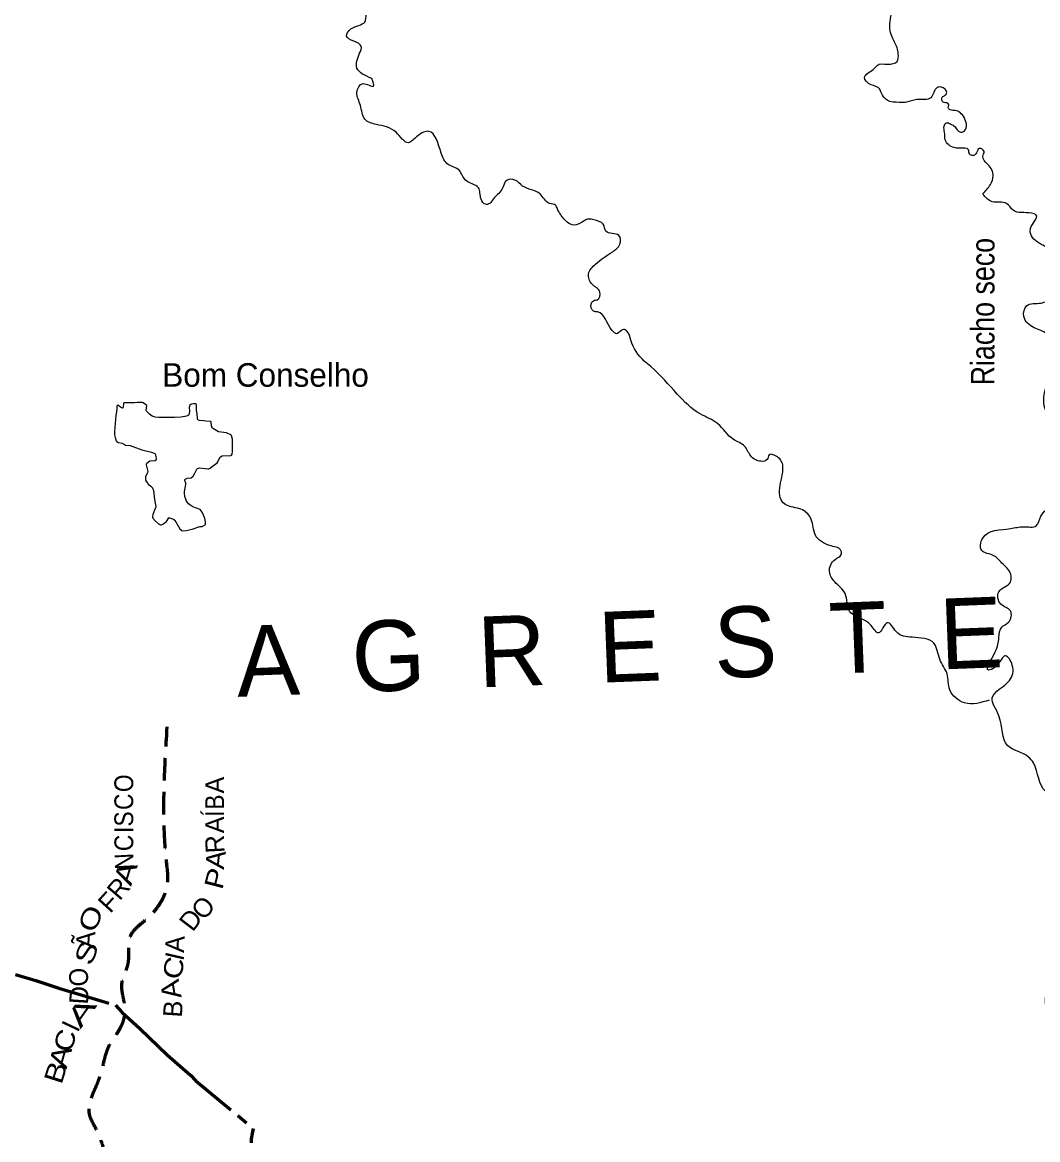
# Model space of a CAD drawing. Extents: x -1643653 to 4543381, y 1624270 to 13878484.
# Drawn here: x 751465 to 773010, y 8971104 to 8994810 of the extents above; entities that cross this region are included whole.
import ezdxf
from ezdxf.enums import TextEntityAlignment as Align

# ---------------------------------------------------------------- set-up
doc = ezdxf.new("R2010")
doc.units = 0
doc.header["$LTSCALE"] = 160
doc.linetypes.add('LONG_DASH_SHORT_DASH', pattern=[9.9, 6, -1.2, 1.5, -1.2])
doc.linetypes.add('MEDIUM_DASHED', pattern=[4.5, 3, -1.5])
for name, color, linetype, lineweight in [('10', 7, 'MEDIUM_DASHED', 60), ('21', 7, 'Continuous', 25), ('24', 7, 'Continuous', 25), ('60', 7, 'Continuous', 13), ('7', 7, 'LONG_DASH_SHORT_DASH', 60)]:
    doc.layers.add(name, color=color, linetype=linetype, lineweight=lineweight)
for name, color, linetype in [('41', 7, 'Continuous'), ('49', 7, 'Continuous'), ('55', 7, 'Continuous')]:
    doc.layers.add(name, color=color, linetype=linetype)

msp = doc.modelspace()

# ---------------------------------------------------------------- linework, layer by layer
at = {"layer": '10'}
msp.add_spline([(753353.8, 8967411.3), (753402.1, 8967459.7), (753447.5, 8967537.9), (753569.9, 8968137.4), (753569.9, 8968618.2), (753685.3, 8969252.9), (753896.8, 8969522.2), (753935.3, 8969791.5), (753646.8, 8970214.6), (753242.9, 8970791.6), (753050.6, 8971291.7), (752896.7, 8971618.7), (753127.5, 8972484.2), (753300.6, 8973080.5), (753550.6, 8973484.4), (753646.8, 8973869.1), (753589.1, 8974215.3), (753589.1, 8974484.5), (753704.5, 8974811.5), (753723.7, 8975177), (753762.2, 8975427), (754089.2, 8975773.2), (754377.7, 8976100.2), (754550.8, 8976561.8), (754531.6, 8976946.5), (754538.8, 8979865.5)], degree=3, dxfattribs=at)
at = {"layer": '21'}
for points in [[(754106.5, 8986680.5), (754028.4, 8986735.9), (754008.6, 8986741.8), (753959.7, 8986746.4), (753911.5, 8986745.8), (753847.3, 8986736.2), (753617.4, 8986734.1), (753610.5, 8986721), (753603, 8986636.5), (753598.5, 8986625.7), (753593.3, 8986622.8), (753548.2, 8986646.6), (753513.2, 8986676.1), (753489.4, 8986684.9), (753479.3, 8986681.3), (753473.2, 8986665.5), (753471.1, 8986603.5), (753456.9, 8986505.7)], [(755463.7, 8986343), (755359.2, 8986349), (755313.3, 8986357.6), (755225.2, 8986360), (755200.7, 8986372.1), (755184.6, 8986391.3), (755179.9, 8986406.1), (755172.6, 8986505.7), (755160.5, 8986575.6), (755157.9, 8986696.6), (755154.6, 8986709), (755144.5, 8986717.7), (755099.3, 8986716.4), (755051.6, 8986708.7), (755037.8, 8986701.8), (755021.5, 8986685), (755006.7, 8986638.5), (755009.5, 8986566), (755006.7, 8986501), (755001.5, 8986483.7), (754990.6, 8986472.3), (754949.5, 8986450.8), (754835.7, 8986433), (754694, 8986426.1), (754358.5, 8986424.1), (754285.6, 8986433.3), (754221.1, 8986453.4), (754162.9, 8986497.5), (754099.2, 8986557.1), (754095.9, 8986575.3), (754106.5, 8986680.5)], [(753456.9, 8986505.7), (753451.7, 8986470.4), (753417.7, 8986131.5), (753423.5, 8986054.9), (753436.8, 8985998.3), (753459.2, 8985928.4), (753468.7, 8985916.1), (753504.7, 8985896.3), (753581.4, 8985882.6), (753631.7, 8985851.6), (753656, 8985840.8), (753753.8, 8985828.2), (754001.5, 8985739.7), (754207.2, 8985690), (754265.7, 8985669.4), (754278, 8985661.9), (754285, 8985652.1), (754300.8, 8985600.5), (754303.9, 8985539.2), (754296.8, 8985521.3), (754284.9, 8985509.2), (754274.8, 8985505.2), (754168.7, 8985495.8), (754105.6, 8985448.6), (754092.8, 8985434.4), (754092.1, 8985422.4), (754127.9, 8985277.1), (754124.1, 8985252.2), (754079.9, 8985172.5), (754077, 8985121), (754081, 8985097.3), (754105.4, 8985051.6), (754127.7, 8985027.4), (754137.5, 8985008), (754181.1, 8984978.6), (754227.8, 8984934.9), (754247.5, 8984880.2), (754270.2, 8984687.2), (754283.8, 8984614.6), (754295.2, 8984523.1), (754286.3, 8984492.2), (754235.9, 8984364.6), (754229.1, 8984308.5), (754236.8, 8984288.9), (754289.6, 8984223.1), (754353.6, 8984172.3), (754396.8, 8984149.9), (754417.7, 8984147.5), (754444.8, 8984159.8), (754522, 8984218.2), (754577.1, 8984295.8), (754587.6, 8984296.2), (754671, 8984266.2), (754701.7, 8984245.3), (754806.1, 8984064), (754848, 8984027.6), (754866.2, 8984018.8), (754939.3, 8984028), (755065.3, 8984056.9), (755228.7, 8984110.9), (755278.6, 8984115.5), (755332.8, 8984138), (755345.8, 8984148.7), (755349.7, 8984161.8), (755350.8, 8984206.2), (755335.7, 8984282.9), (755311.7, 8984351.5), (755283.8, 8984415.4), (755236.2, 8984470.9), (755082.2, 8984529.5), (755020.7, 8984572.5), (754993.5, 8984596.2), (754950, 8984652.2), (754938.2, 8984672.7), (754911.7, 8984751.8), (754902.8, 8984821.5), (754904.4, 8984856.5), (754929.6, 8984958.3), (754935.6, 8985018.6), (754933.4, 8985034.7), (754913.9, 8985089.7), (754913.2, 8985105.4), (754922.8, 8985115.9), (754969.6, 8985136.5), (755045.1, 8985148.2), (755045.1, 8985148.2), (755089.7, 8985177.8), (755121.3, 8985227.3), (755167.3, 8985327.7), (755182.7, 8985345.9), (755206, 8985350), (755225, 8985358.8), (755398.6, 8985334.3), (755419.4, 8985337.3), (755454.3, 8985352.7), (755491.7, 8985386.9), (755598.4, 8985464.8), (755610.1, 8985482.6), (755653.5, 8985579.7), (755666.6, 8985594.3), (755707, 8985610.9)], [(755707, 8985610.9), (755890.2, 8985621.7), (755905.4, 8985627.2), (755915.8, 8985647.5), (755925.1, 8985701.8), (755922.8, 8985964.8), (755902.2, 8986043.6), (755886.2, 8986060.2), (755799.9, 8986101.9), (755630.8, 8986122.8), (755520.9, 8986187.7), (755503.2, 8986203.3), (755475.9, 8986240.2), (755469.1, 8986332.7), (755463.7, 8986343), (755463.7, 8986343)]]:
    msp.add_lwpolyline(points, dxfattribs=at)
at = {"layer": '21', "lineweight": 13}
for points in [[(753456.9, 8986505.7), (753451.7, 8986470.4), (753417.7, 8986131.5), (753423.5, 8986054.9), (753436.8, 8985998.3), (753459.2, 8985928.4), (753468.7, 8985916.1), (753504.7, 8985896.3), (753581.4, 8985882.6), (753631.7, 8985851.6), (753656, 8985840.8), (753753.8, 8985828.2), (754001.5, 8985739.7), (754207.2, 8985690), (754265.7, 8985669.4), (754278, 8985661.9), (754285, 8985652.1), (754300.8, 8985600.5), (754303.9, 8985539.2), (754296.8, 8985521.3), (754284.9, 8985509.2), (754274.8, 8985505.2), (754168.7, 8985495.8), (754105.6, 8985448.6), (754092.8, 8985434.4), (754092.1, 8985422.4), (754127.9, 8985277.1), (754124.1, 8985252.2), (754079.9, 8985172.5), (754077, 8985121), (754081, 8985097.3), (754105.4, 8985051.6), (754127.7, 8985027.4), (754137.5, 8985008), (754181.1, 8984978.6), (754227.8, 8984934.9), (754247.5, 8984880.2), (754270.2, 8984687.2), (754283.8, 8984614.6), (754295.2, 8984523.1), (754286.3, 8984492.2), (754235.9, 8984364.6), (754229.1, 8984308.5), (754236.8, 8984288.9), (754289.6, 8984223.1), (754353.6, 8984172.3), (754396.8, 8984149.9), (754417.7, 8984147.5), (754444.8, 8984159.8), (754522, 8984218.2), (754577.1, 8984295.8), (754587.6, 8984296.2), (754671, 8984266.2), (754701.7, 8984245.3), (754806.1, 8984064), (754848, 8984027.6), (754866.2, 8984018.8), (754939.3, 8984028), (755065.3, 8984056.9), (755228.7, 8984110.9), (755278.6, 8984115.5), (755332.8, 8984138), (755345.8, 8984148.7), (755349.7, 8984161.8), (755350.8, 8984206.2), (755335.7, 8984282.9), (755311.7, 8984351.5), (755283.8, 8984415.4), (755236.2, 8984470.9), (755082.2, 8984529.5), (755020.7, 8984572.5), (754993.5, 8984596.2), (754950, 8984652.2), (754938.2, 8984672.7), (754911.7, 8984751.8), (754902.8, 8984821.5), (754904.4, 8984856.5), (754929.6, 8984958.3), (754935.6, 8985018.6), (754933.4, 8985034.7), (754913.9, 8985089.7), (754913.2, 8985105.4), (754922.8, 8985115.9), (754969.6, 8985136.5), (755045.1, 8985148.2), (755045.1, 8985148.2), (755089.7, 8985177.8), (755121.3, 8985227.3), (755167.3, 8985327.7), (755182.7, 8985345.9), (755206, 8985350), (755225, 8985358.8), (755398.6, 8985334.3), (755419.4, 8985337.3), (755454.3, 8985352.7), (755491.7, 8985386.9), (755598.4, 8985464.8), (755610.1, 8985482.6), (755653.5, 8985579.7), (755666.6, 8985594.3), (755707, 8985610.9)], [(755707, 8985610.9), (755890.2, 8985621.7), (755905.4, 8985627.2), (755915.8, 8985647.5), (755925.1, 8985701.8), (755922.8, 8985964.8), (755902.2, 8986043.6), (755886.2, 8986060.2), (755799.9, 8986101.9), (755630.8, 8986122.8), (755520.9, 8986187.7), (755503.2, 8986203.3), (755475.9, 8986240.2), (755469.1, 8986332.7), (755463.7, 8986343), (755463.7, 8986343)]]:
    msp.add_lwpolyline(points, dxfattribs=at)
at = {"layer": '24'}
for points in [[(758879.2, 8993619.3), (758566.2, 8993840.3), (758621.5, 8994153.5), (758658.3, 8994300.8), (758345.4, 8994521.8), (758437.4, 8994669.2), (758731.9, 8994816.6), (758750.3, 8995184.9), (758787.1, 8995406), (758731.9, 8995645.4), (758842.3, 8995903.3), (758842.3, 8996069), (758658.3, 8996087.5), (758511, 8995866.4), (758327, 8995884.8), (758253.3, 8996087.5), (758087.7, 8996179.5), (758069.2, 8995958.5), (757977.2, 8995903.3), (757811.6, 8996087.5), (757811.6, 8996363.7), (757811.6, 8996492.7), (757682.7, 8996584.8), (757314.6, 8996658.4), (757259.3, 8996842.6), (757259.3, 8997026.8), (757038.5, 8997303.1), (756983.2, 8997542.5), (757167.3, 8997855.7), (757130.5, 8998187.2), (757001.6, 8998371.4), (757112.1, 8998702.9), (757222.5, 8998942.4), (757056.9, 8999181.8), (757056.9, 8999384.4), (756854.4, 8999476.5), (756836, 8999789.6), (757001.6, 8999955.4), (757093.7, 9000231.7), (757222.5, 9000581.7), (757425, 9000729), (757572.3, 9000968.5), (757719.5, 9000968.5), (757737.9, 9001171.1), (757682.7, 9001484.2), (757811.6, 9001668.4), (757866.8, 9001981.5), (758050.8, 9002313), (758290.1, 9002405.1), (758474.2, 9002294.6), (758676.7, 9002478.8), (759044.8, 9003105), (759192.1, 9003123.5), (759339.3, 9003289.2), (759541.8, 9003436.6)], [(771454.5, 8992786.6), (771363.4, 8992894.2), (771259, 8992936.7), (771154.7, 8992956), (771112.2, 8992994.7), (771127.6, 8993052.7), (771104.5, 8993091.4), (771004, 8993114.6), (770984.7, 8993219), (771054.2, 8993269.2), (771081.3, 8993323.4), (770961.5, 8993435.5), (770876.5, 8993423.9), (770745.1, 8993211.2), (770443.7, 8993172.6), (770227.3, 8993114.6), (770072.7, 8993110.7), (769817.6, 8993157.1), (769694, 8993307.9), (769655.3, 8993400.7), (769477.6, 8993485.8), (769338.5, 8993640.5), (769404.2, 8993733.3), (769520.1, 8993806.7), (769601.2, 8993895.7), (769833.1, 8993922.7), (770026.3, 8993980.7), (770053.4, 8994139.3), (770026.3, 8994270.7), (769918.1, 8994514.3), (769875.6, 8994672.9), (769914.3, 8995094.4), (769910.4, 8995237.4), (769910.4, 8995419.2), (769879.5, 8995477.2), (769829.2, 8995523.6), (769713.3, 8995519.7), (769655.3, 8995566.1), (769425.4, 8995635.7), (769162.7, 8995774.9), (769023.6, 8995991.4), (768760.8, 8996006.9), (768683.5, 8995991.4), (768498, 8996238.9), (768266.2, 8996177), (768018.8, 8995991.4), (767941.5, 8995759.4), (767740.6, 8995620.2), (767632.4, 8995697.6), (767323.3, 8995728.5), (767431.5, 8995945), (767663.3, 8996022.4), (767771.5, 8996238.9), (767987.9, 8996393.6), (768157.9, 8996455.5), (768142.5, 8996548.2), (767941.5, 8996656.5), (767833.3, 8996702.9), (767323.3, 8996409.1), (767014.1, 8996625.6), (766998.7, 8996981.3), (767091.4, 8997151.5), (766735.9, 8997136), (766148.5, 8997120.5), (766086.7, 8997429.9), (766210.3, 8997770.2), (766117.6, 8997924.8), (765932.1, 8997832), (765715.7, 8997940.3), (765823.9, 8998218.7), (765793, 8998435.2), (765793, 8998729.1), (765576.6, 8998837.4), (765375.7, 8998775.5), (765252, 8998992.1), (765329.3, 8999409.7), (765004.7, 8999517.9), (764772.8, 8999332.3), (764633.7, 8998976.6), (764278.2, 8998667.2), (764061.8, 8998760), (764200.9, 8999440.6), (764479.1, 8999657.1), (764602.8, 8999873.7), (764231.8, 9000059.3), (763690.8, 9000616.1), (763752.6, 9000832.6), (763969, 9001018.2), (764200.9, 9001126.5), (764355.5, 9001528.7), (764711, 9001606)], [(771983.6, 8980431.6), (771458.1, 8980369.7), (771148.9, 8980648.1), (771087.1, 8980988.4), (770932.5, 8981297.7), (770808.9, 8981638), (770345.2, 8981761.8), (770005.1, 8981885.5), (769819.6, 8982071.1), (769634.1, 8981854.6), (769479.5, 8982009.2), (769015.8, 8982318.6), (768923.1, 8982689.8), (768706.7, 8982937.2), (768593.5, 8983157.4), (768713.2, 8983415.3), (768842, 8983516.6), (768842, 8983590.2), (768630.3, 8983700.8), (768289.8, 8983940.2), (768207, 8984262.5), (768022.9, 8984465.2), (767700.8, 8984557.2), (767590.3, 8984640.1), (767553.5, 8985036.1), (767599.5, 8985266.4), (767599.5, 8985422.9), (767461.5, 8985607.1), (767314.2, 8985634.8), (767268.2, 8985533.4), (767139.4, 8985496.6), (766918.5, 8985616.3), (766789.6, 8985818.9), (766559.5, 8985957.1), (766219, 8986297.8), (765850.9, 8986500.4), (765363.1, 8986924.1), (764801.7, 8987504.3), (764663.6, 8987624), (764378.3, 8988066), (764295.5, 8988259.4), (764221.8, 8988296.3), (764083.8, 8988204.2), (763982.5, 8988268.6), (763669.6, 8988664.7), (763586.8, 8988683.1), (763540.8, 8988848.8), (763605.2, 8988913.3), (763665, 8988922.5), (763720.2, 8989088.3), (763554.6, 8989254.1), (763480.9, 8989475.1), (763628.2, 8989677.7), (763977.9, 8989935.6), (764143.6, 8990101.3), (764125.2, 8990285.5), (763849.1, 8990377.6), (763793.9, 8990525), (763591.4, 8990617.1), (763480.9, 8990635.5), (763260.1, 8990525), (763094.4, 8990525), (762965.5, 8990635.5), (762818.3, 8990856.5), (762781.5, 8990930.2), (762652.6, 8990967), (762450.1, 8991169.6), (762082, 8991335.4), (761916.3, 8991464.3), (761750.7, 8991464.3), (761640.2, 8991261.7), (761456.2, 8991059.1), (761382.5, 8990967), (761290.5, 8990948.6), (761198.5, 8991059.1), (761143.2, 8991298.6), (760867.1, 8991464.3), (760738.3, 8991666.9), (760499, 8991795.9), (760351.7, 8992035.3), (760094, 8992495.8), (759854.7, 8992403.7), (759652.3, 8992256.3), (759394.6, 8992477.3), (758971.2, 8992643.1), (758731.9, 8992753.6), (758639.9, 8993048.3), (758566.2, 8993324.6), (758695.1, 8993508.8), (758916, 8993453.6), (758879.2, 8993619.3)], [(771844.7, 8991166.7), (772006.9, 8991369.5), (772067.7, 8991552), (771954.6, 8991796), (771846.4, 8991966.2), (771873.5, 8992066.7), (771842.5, 8992113.1), (771769.1, 8992132.4), (771715, 8992043.5), (771645.5, 8991985.5), (771564.3, 8992012.6), (771545, 8992101.5), (771351.8, 8992140.2), (771235.8, 8992151.8), (771050.3, 8992314.2), (771034.9, 8992480.4), (771023.3, 8992604.2), (771077.4, 8992677.6), (771162.4, 8992654.4), (771232, 8992615.8), (771332.5, 8992499.8), (771382.7, 8992476.6), (771456.1, 8992507.5), (771498.6, 8992646.7), (771452.2, 8992793.6)], [(774675.9, 8971457.7), (774621.3, 8971839.9), (774398.4, 8971961.6), (774175.5, 8972002.1), (774175.5, 8972387.4), (774317.3, 8972793), (774398.4, 8972955.3), (774297.1, 8973158.1), (773891.7, 8973300), (773810.7, 8973421.7), (773506.6, 8973847.6), (773222.9, 8973888.2), (773182.4, 8974151.8), (773222.9, 8974314), (773466.1, 8974334.3), (773648.5, 8974557.4), (773871.5, 8974618.2), (774094.4, 8974435.7), (774317.3, 8974598), (774540.3, 8974902.2), (774722.7, 8975105), (774580.8, 8975226.6), (774175.5, 8975186.1), (773749.8, 8975429.4), (773668.8, 8975936.4), (773385, 8976402.9), (773324.2, 8976930.1), (773486.4, 8977538.5), (773810.7, 8978248.3), (773810.7, 8978430.9), (773466.1, 8978430.9), (773182.4, 8978491.7), (772918.9, 8979100.1), (772817.6, 8979221.8), (772371.7, 8979465.1), (772189.3, 8980093.8), (772047.4, 8980479.1), (772412.2, 8980844.2), (772473, 8981168.7), (772331.2, 8981371.5), (772108.2, 8981128.1), (771966.3, 8981067.3), (772108.2, 8981452.6), (772189.3, 8981756.8), (772250.1, 8981979.9), (772392, 8982081.3), (772432.5, 8982324.6), (772229.8, 8982466.6), (772189.3, 8982730.2), (772432.5, 8982933), (772392, 8983196.7), (772250.1, 8983338.6), (772067.7, 8983500.8), (771824.5, 8983602.2), (771844.8, 8983865.9), (772432.5, 8984068.7), (772716.2, 8984109.2), (772979.7, 8984129.5), (773081, 8984332.3), (773486.4, 8984596), (773932.3, 8984839.3), (773932.3, 8985062.4), (773830.9, 8985244.9), (773830.9, 8985488.3), (774175.5, 8985812.8), (774337.6, 8985934.5), (774195.7, 8986117), (774114.7, 8986340.1), (773830.9, 8986299.5), (773668.8, 8986238.7), (773304, 8986380.6), (773141.8, 8986867.3), (773364.8, 8987475.7), (773405.3, 8987840.8), (773202.6, 8988205.8), (772939.2, 8988327.5), (772716.2, 8988570.8), (772777, 8988793.9), (773081, 8988854.8), (773324.2, 8988956.2), (773526.9, 8989098.1), (773385, 8989605.1), (773283.7, 8989970.2), (773000, 8990152.7), (772858.1, 8990436.6), (772979.7, 8990720.5), (772878.4, 8990761.1), (772493.3, 8990821.9), (772351.4, 8990963.9), (772047.4, 8991004.4), (771844.7, 8991166.7)]]:
    msp.add_spline(points, degree=3, dxfattribs=at)
at = {"layer": '60', "lineweight": 25}
msp.add_spline([(814781, 9009175.5), (814787.2, 9009173.4), (814796.9, 9009173.4), (814799.4, 9009172.4), (814805.1, 9009174.5), (814805.6, 9009176.5), (814811.7, 9009179.5), (814811.7, 9009179.5), (814801.5, 9009181), (814790.7, 9009181.5), (814784.1, 9009183.1), (814777.4, 9009185.1), (814778.4, 9009175.5)], degree=3, dxfattribs=at)
at = {"layer": '7'}
msp.add_lwpolyline([(745697.7, 8975189), (745697.7, 8975189), (746278.3, 8975226), (747060.9, 8975214.3), (747626.8, 8975234.9), (748067.1, 8975233), (748078.4, 8975249.4), (748961.7, 8975196.1), (749681.4, 8975121.3), (750036, 8975026.7), (750271.4, 8974951.8), (751320.7, 8974608), (751750.1, 8974483.8), (752242.5, 8974318.8), (752380.7, 8974278), (753439.5, 8973954.2), (753583.6, 8973799.8), (753961.2, 8973460.6), (754538, 8972903.3), (755030, 8972474.8), (755147.7, 8972349.6), (756362.8, 8971344), (756320.3, 8971125.1), (756323.8, 8971036.6)], dxfattribs=at)

# ---------------------------------------------------------------- texts
at = {"layer": '10'}
for s, rotation, width, p in [('O', 90.036, 0.9, (753817.8, 8978665.2)), ('C', 90.036, 0.9, (753818, 8978272.4)), ('B', 90.036, 0.9, (755746.5, 8978265.8)), ('S', 90.036, 0.9, (753818.2, 8977908.6)), ('Í', 90.036, 0.85, (755746.7, 8978022)), ('C', 90.036, 0.9, (753818.6, 8977399.4)), ('A', 83.512, 1.1, (755762.6, 8977022)), ('N', 92.943, 0.9, (753827.9, 8977019.2)), ('A', 72.093, 1.35, (753844.7, 8976698.2)), ('P', 75.752, 1.2, (755758.5, 8976597.7)), ('O', 68.654, 1.3, (753100.6, 8975721.6)), ('S', 68.232, 1.35, (753011.4, 8974993.7)), ('C', 75.108, 1.2, (754866.1, 8974693.7)), ('O', 92.819, 0.95, (752858.4, 8974562.2)), ('A', 99.428, 1.15, (754812.1, 8974324.5)), ('A', 54.756, 1.75, (752879.4, 8973696.6)), ('C', 73.461, 1.2, (752562.8, 8973151.1)), ('A', 74.159, 1.3, (752463.3, 8972809.8)), ('B', 72.657, 1.25, (752362.1, 8972471.4))]:
    msp.add_text(s, height=400, rotation=rotation, dxfattribs=dict(at, width=width)).set_placement(p, align=Align.CENTER)
for s, rotation, p in [('A', 90.036, (755746.3, 8978627.4)), ('A', 90.036, (755746.8, 8977783.2)), ('I', 90.036, (753818.4, 8977676.6)), ('R', 92.943, (755748.6, 8977384.2)), ('R', 49.429, (753655.3, 8976304.3)), ('F', 47.713, (753441.2, 8976008.7)), ('O', 47.713, (755448.4, 8975892)), ('D', 52.701, (755198, 8975649.5)), ('Ã', 87.425, (753008, 8975336.6)), ('A', 87.425, (754900.6, 8975243.2)), ('I', 77.053, (754893.2, 8974952.8)), ('D', 86.239, (752868.5, 8974156.8)), ('B', 86.239, (754860, 8973866)), ('I', 64.893, (752674.8, 8973428.8))]:
    msp.add_text(s, height=400, rotation=rotation, dxfattribs=at).set_placement(p, align=Align.CENTER)
at = {"layer": '41'}
msp.add_text('Bom Conselho', height=500, dxfattribs=at).set_placement((754433.5, 8987078.3))
at = {"layer": '49', "width": 0.85}
msp.add_text('Riacho seco', height=500, rotation=90, dxfattribs=at).set_placement((772094.2, 8988672), align=Align.CENTER)
at = {"layer": '55'}
msp.add_text('A  G  R  E  S  T  E', height=1500, rotation=2.229, dxfattribs=at).set_placement((756032.3, 8980498.3))

doc.saveas('drawing.dxf')
